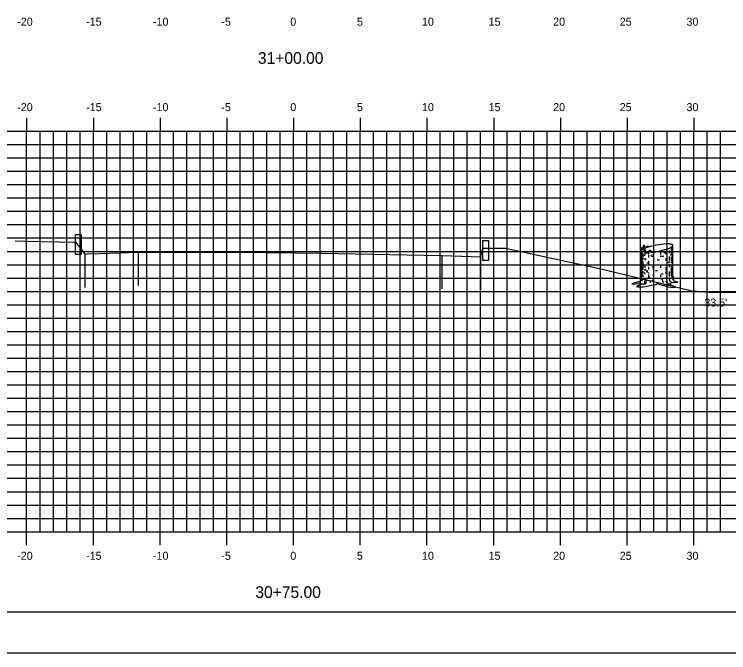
# Model space of a CAD drawing. Extents: x 1037709 to 1037879, y 394883 to 394993.
# Drawn here: x 1037771.2 to 1037824.8, y 394882.6 to 394930.4 of the extents above; entities that cross this region are included whole.
import ezdxf

# ---------------------------------------------------------------- set-up
doc = ezdxf.new("R2010")
doc.units = 0
for name, color, linetype in [('BORDER', 7, 'Continuous'), ('D_Text_Standard', 7, 'Continuous'), ('H_V ANNOTATION', 7, 'Continuous'), ('MAJOR', 7, 'Continuous'), ('MINOR', 7, 'Continuous'), ('PLOT BOUNDARY', 7, 'Continuous'), ('S_Curb_Type_1', 7, 'Continuous'), ('S_Roadway_Centerline', 7, 'Continuous'), ('S_Roadway_Edge_Pavement', 7, 'Continuous'), ('S_Roadway_Edge_TW', 7, 'Continuous'), ('S_Trees_Decid_Pay', 7, 'Continuous')]:
    doc.layers.add(name, color=color, linetype=linetype)

msp = doc.modelspace()

# ---------------------------------------------------------------- linework, layer by layer
at = {"layer": 'BORDER'}
msp.add_line((1037717.157, 394885.686), (1037877.157, 394885.686), dxfattribs=at)
at = {"layer": 'MAJOR'}
for p, q in [((1037772.157, 394922.688), (1037772.157, 394921.686)), ((1037777.157, 394922.688), (1037777.157, 394921.686)), ((1037782.157, 394922.688), (1037782.157, 394921.686)), ((1037787.157, 394922.688), (1037787.157, 394921.686)), ((1037792.157, 394922.688), (1037792.157, 394921.686)), ((1037797.157, 394922.688), (1037797.157, 394921.686)), ((1037802.157, 394922.688), (1037802.157, 394921.686)), ((1037807.157, 394922.688), (1037807.157, 394921.686)), ((1037812.157, 394922.688), (1037812.157, 394921.686)), ((1037817.157, 394922.688), (1037817.157, 394921.686)), ((1037822.157, 394922.688), (1037822.157, 394921.686)), ((1037722.157, 394921.686), (1037862.157, 394921.686)), ((1037772.157, 394891.686), (1037772.157, 394921.686)), ((1037777.157, 394891.686), (1037777.157, 394921.686)), ((1037782.157, 394891.686), (1037782.157, 394921.686)), ((1037787.157, 394891.686), (1037787.157, 394921.686)), ((1037792.157, 394891.686), (1037792.157, 394921.686)), ((1037797.157, 394891.686), (1037797.157, 394921.686)), ((1037802.157, 394891.686), (1037802.157, 394921.686)), ((1037807.157, 394891.686), (1037807.157, 394921.686)), ((1037812.157, 394891.686), (1037812.157, 394921.686)), ((1037817.157, 394891.686), (1037817.157, 394921.686)), ((1037822.157, 394891.686), (1037822.157, 394921.686)), ((1037722.157, 394916.686), (1037862.157, 394916.686)), ((1037722.157, 394911.686), (1037862.157, 394911.686)), ((1037722.157, 394906.686), (1037862.157, 394906.686)), ((1037722.157, 394901.686), (1037862.157, 394901.686)), ((1037722.157, 394896.686), (1037862.157, 394896.686)), ((1037722.157, 394891.686), (1037862.157, 394891.686)), ((1037772.157, 394890.684), (1037772.157, 394891.686)), ((1037777.157, 394890.684), (1037777.157, 394891.686)), ((1037782.157, 394890.684), (1037782.157, 394891.686)), ((1037787.157, 394890.684), (1037787.157, 394891.686)), ((1037792.157, 394890.684), (1037792.157, 394891.686)), ((1037797.157, 394890.684), (1037797.157, 394891.686)), ((1037802.157, 394890.684), (1037802.157, 394891.686)), ((1037807.157, 394890.684), (1037807.157, 394891.686)), ((1037812.157, 394890.684), (1037812.157, 394891.686)), ((1037817.157, 394890.684), (1037817.157, 394891.686)), ((1037822.157, 394890.684), (1037822.157, 394891.686))]:
    msp.add_line(p, q, dxfattribs=at)
at = {"layer": 'MINOR'}
for p, q in [((1037773.157, 394891.686), (1037773.157, 394921.686)), ((1037774.157, 394891.686), (1037774.157, 394921.686)), ((1037775.157, 394891.686), (1037775.157, 394921.686)), ((1037776.157, 394891.686), (1037776.157, 394921.686)), ((1037778.157, 394891.686), (1037778.157, 394921.686)), ((1037779.157, 394891.686), (1037779.157, 394921.686)), ((1037780.157, 394891.686), (1037780.157, 394921.686)), ((1037781.157, 394891.686), (1037781.157, 394921.686)), ((1037783.157, 394891.686), (1037783.157, 394921.686)), ((1037784.157, 394891.686), (1037784.157, 394921.686)), ((1037785.157, 394891.686), (1037785.157, 394921.686)), ((1037786.157, 394891.686), (1037786.157, 394921.686)), ((1037788.157, 394891.686), (1037788.157, 394921.686)), ((1037789.157, 394891.686), (1037789.157, 394921.686)), ((1037790.157, 394891.686), (1037790.157, 394921.686)), ((1037791.157, 394891.686), (1037791.157, 394921.686)), ((1037793.157, 394891.686), (1037793.157, 394921.686)), ((1037794.157, 394891.686), (1037794.157, 394921.686)), ((1037795.157, 394891.686), (1037795.157, 394921.686)), ((1037796.157, 394891.686), (1037796.157, 394921.686)), ((1037798.157, 394891.686), (1037798.157, 394921.686)), ((1037799.157, 394891.686), (1037799.157, 394921.686)), ((1037800.157, 394891.686), (1037800.157, 394921.686)), ((1037801.157, 394891.686), (1037801.157, 394921.686)), ((1037803.157, 394891.686), (1037803.157, 394921.686)), ((1037804.157, 394891.686), (1037804.157, 394921.686)), ((1037805.157, 394891.686), (1037805.157, 394921.686)), ((1037806.157, 394891.686), (1037806.157, 394921.686)), ((1037808.157, 394891.686), (1037808.157, 394921.686)), ((1037809.157, 394891.686), (1037809.157, 394921.686)), ((1037810.157, 394891.686), (1037810.157, 394921.686)), ((1037811.157, 394891.686), (1037811.157, 394921.686)), ((1037813.157, 394891.686), (1037813.157, 394921.686)), ((1037814.157, 394891.686), (1037814.157, 394921.686)), ((1037815.157, 394891.686), (1037815.157, 394921.686)), ((1037816.157, 394891.686), (1037816.157, 394921.686)), ((1037818.157, 394891.686), (1037818.157, 394921.686)), ((1037819.157, 394891.686), (1037819.157, 394921.686)), ((1037820.157, 394891.686), (1037820.157, 394921.686)), ((1037821.157, 394891.686), (1037821.157, 394921.686)), ((1037823.157, 394891.686), (1037823.157, 394921.686)), ((1037824.157, 394891.686), (1037824.157, 394921.686)), ((1037722.157, 394920.686), (1037862.157, 394920.686)), ((1037722.157, 394919.686), (1037862.157, 394919.686)), ((1037722.157, 394918.686), (1037862.157, 394918.686)), ((1037722.157, 394917.686), (1037862.157, 394917.686)), ((1037722.157, 394915.686), (1037862.157, 394915.686)), ((1037722.157, 394914.686), (1037862.157, 394914.686)), ((1037722.157, 394913.686), (1037862.157, 394913.686)), ((1037722.157, 394912.686), (1037862.157, 394912.686)), ((1037722.157, 394910.686), (1037862.157, 394910.686)), ((1037722.157, 394909.686), (1037862.157, 394909.686)), ((1037722.157, 394908.686), (1037862.157, 394908.686)), ((1037722.157, 394907.686), (1037862.157, 394907.686)), ((1037722.157, 394905.686), (1037862.157, 394905.686)), ((1037722.157, 394904.686), (1037862.157, 394904.686)), ((1037722.157, 394903.686), (1037862.157, 394903.686)), ((1037722.157, 394902.686), (1037862.157, 394902.686)), ((1037722.157, 394900.686), (1037862.157, 394900.686)), ((1037722.157, 394899.686), (1037862.157, 394899.686)), ((1037722.157, 394898.686), (1037862.157, 394898.686)), ((1037722.157, 394897.686), (1037862.157, 394897.686)), ((1037722.157, 394895.686), (1037862.157, 394895.686)), ((1037722.157, 394894.686), (1037862.157, 394894.686)), ((1037722.157, 394893.686), (1037862.157, 394893.686)), ((1037722.157, 394892.686), (1037862.157, 394892.686))]:
    msp.add_line(p, q, dxfattribs=at)
at = {"layer": 'PLOT BOUNDARY'}
msp.add_lwpolyline([(1037709.064, 394882.627), (1037879.064, 394882.627), (1037879.064, 394992.627), (1037709.064, 394992.627)], close=True, dxfattribs=at)
at = {"layer": 'S_Curb_Type_1'}
for points in [[(1037775.828, 394913.952), (1037776.244, 394913.952), (1037776.244, 394912.452), (1037775.828, 394912.452)], [(1037806.351, 394913.51), (1037806.768, 394913.51), (1037806.768, 394912.01), (1037806.351, 394912.01)]]:
    msp.add_lwpolyline(points, close=True, dxfattribs=at)
at = {"layer": 'S_Roadway_Centerline'}
msp.add_lwpolyline([(1037771.303, 394913.468), (1037772.043, 394913.454), (1037775.828, 394913.369), (1037776.383, 394912.646), (1037776.528, 394912.481), (1037776.688, 394912.497), (1037777.677, 394912.527), (1037780.514, 394912.634), (1037790.122, 394912.588), (1037792.25, 394912.579), (1037794.199, 394912.547), (1037803.27, 394912.372), (1037804.774, 394912.324), (1037806.176, 394912.282), (1037806.341, 394912.89), (1037806.351, 394912.926), (1037806.4, 394912.926), (1037808.033, 394912.919), (1037815.077, 394911.41), (1037822.032, 394909.722), (1037823.625, 394909.598), (1037825.706, 394909.621)], dxfattribs=at)
at = {"layer": 'S_Roadway_Edge_Pavement'}
for p, q in [((1037776.528, 394912.481), (1037776.528, 394909.981)), ((1037806.176, 394912.282), (1037806.176, 394909.782))]:
    msp.add_line(p, q, dxfattribs=at)
at = {"layer": 'S_Roadway_Edge_TW'}
for p, q in [((1037780.514, 394912.634), (1037780.514, 394910.134)), ((1037803.27, 394912.372), (1037803.27, 394909.872))]:
    msp.add_line(p, q, dxfattribs=at)
at = {"layer": 'S_Trees_Decid_Pay'}
for p, q in [((1037820.53, 394913.04), (1037820.53, 394912.92)), ((1037818.256, 394912.637), (1037818.256, 394912.382)), ((1037818.405, 394912.837), (1037818.405, 394912.662)), ((1037818.49, 394912.588), (1037818.49, 394912.383)), ((1037818.751, 394912.59), (1037818.751, 394912.471)), ((1037819.662, 394912.728), (1037819.662, 394912.448)), ((1037820.045, 394912.829), (1037820.045, 394912.742)), ((1037820.045, 394912.601), (1037820.045, 394912.462)), ((1037820.317, 394912.742), (1037820.317, 394912.551)), ((1037820.45, 394912.996), (1037820.45, 394912.742)), ((1037820.45, 394912.646), (1037820.45, 394912.382)), ((1037820.53, 394912.868), (1037820.53, 394912.654)), ((1037820.53, 394912.609), (1037820.53, 394912.271)), ((1037818.256, 394912.285), (1037818.256, 394911.816)), ((1037818.342, 394912.491), (1037818.342, 394912.279)), ((1037818.342, 394912.214), (1037818.342, 394912.065)), ((1037818.49, 394912.176), (1037818.49, 394912.022)), ((1037818.751, 394912.419), (1037818.751, 394912.234)), ((1037818.989, 394912.318), (1037818.994, 394912.425)), ((1037819.116, 394912.491), (1037819.116, 394912.311)), ((1037819.662, 394912.382), (1037819.662, 394912.279)), ((1037820.045, 394912.176), (1037820.045, 394911.985)), ((1037820.317, 394912.299), (1037820.317, 394912.022)), ((1037820.317, 394911.977), (1037820.317, 394911.868)), ((1037820.45, 394912.285), (1037820.45, 394911.977)), ((1037820.53, 394912.154), (1037820.53, 394911.793)), ((1037818.256, 394911.765), (1037818.256, 394911.631)), ((1037818.256, 394911.573), (1037818.256, 394911.248)), ((1037818.342, 394911.888), (1037818.342, 394911.588)), ((1037818.342, 394911.55), (1037818.342, 394911.307)), ((1037818.49, 394911.659), (1037818.49, 394911.439)), ((1037818.751, 394911.948), (1037818.751, 394911.719)), ((1037818.751, 394911.521), (1037818.751, 394911.336)), ((1037819.116, 394911.533), (1037819.116, 394911.336)), ((1037819.662, 394911.668), (1037819.662, 394911.447)), ((1037820.045, 394911.505), (1037820.045, 394911.297)), ((1037820.317, 394911.733), (1037820.317, 394911.505)), ((1037820.45, 394911.888), (1037820.45, 394911.822)), ((1037820.45, 394911.588), (1037820.45, 394911.49)), ((1037820.45, 394911.439), (1037820.45, 394911.079)), ((1037820.53, 394911.756), (1037820.53, 394911.307)), ((1037818.256, 394911.219), (1037818.256, 394910.799)), ((1037818.342, 394911.196), (1037818.342, 394911.056)), ((1037818.342, 394910.924), (1037818.342, 394910.768)), ((1037818.49, 394911.339), (1037818.49, 394911.219)), ((1037818.49, 394911.068), (1037818.49, 394910.969)), ((1037818.751, 394911.101), (1037818.751, 394911.025)), ((1037818.751, 394910.947), (1037818.751, 394910.774)), ((1037819.116, 394910.953), (1037819.116, 394910.85)), ((1037819.662, 394910.947), (1037819.662, 394910.774)), ((1037820.045, 394911.175), (1037820.045, 394910.976)), ((1037820.317, 394911.175), (1037820.317, 394910.792)), ((1037820.45, 394911.027), (1037820.45, 394910.86)), ((1037820.53, 394911.242), (1037820.53, 394910.96)), ((1037818.259, 394910.696), (1037818.244, 394910.578)), ((1037820.04, 394910.719), (1037820.12, 394910.587))]:
    msp.add_line(p, q, dxfattribs=at)
for points in [[(1037818.205, 394912.911), (1037818.205, 394910.774), (1037818.185, 394910.632), (1037818.179, 394910.506), (1037818.135, 394910.42), (1037818.043, 394910.37), (1037817.907, 394910.37), (1037817.664, 394910.315), (1037817.497, 394910.265), (1037817.639, 394910.235), (1037817.876, 394910.272), (1037818.086, 394910.259), (1037818.347, 394910.265), (1037818.471, 394910.284), (1037818.502, 394910.241), (1037818.564, 394910.284), (1037818.465, 394910.216), (1037818.23, 394910.191), (1037818, 394910.13), (1037817.87, 394910.059), (1037817.969, 394910.016), (1037818.391, 394910.035), (1037818.669, 394910.078), (1037818.967, 394910.154), (1037819.254, 394910.191), (1037819.359, 394910.191), (1037819.377, 394910.272), (1037819.445, 394910.278), (1037819.612, 394910.191), (1037819.898, 394910.135), (1037820.196, 394910.028), (1037820.656, 394909.979), (1037820.81, 394909.992), (1037820.468, 394910.142), (1037820.265, 394910.173), (1037820.277, 394910.247), (1037820.536, 394910.346), (1037820.712, 394910.377), (1037820.952, 394910.389), (1037820.754, 394910.426), (1037820.693, 394910.463), (1037820.668, 394910.549), (1037820.656, 394910.719), (1037820.611, 394910.805), (1037820.582, 394911.046), (1037820.582, 394913.131)], [(1037818.561, 394912.584), (1037818.553, 394912.728), (1037818.508, 394912.72), (1037818.494, 394913.095), (1037818.399, 394913.103), (1037818.385, 394913.183), (1037818.347, 394912.845), (1037818.302, 394912.94), (1037818.282, 394912.786), (1037818.205, 394912.911), (1037818.211, 394912.721)], [(1037818.584, 394912.95), (1037818.605, 394913.057), (1037818.737, 394913.088), (1037818.744, 394913)], [(1037818.205, 394912.911), (1037818.251, 394912.934), (1037818.273, 394913), (1037818.325, 394913.023), (1037818.359, 394912.948)], [(1037818.723, 394912.588), (1037818.759, 394912.691), (1037818.825, 394912.697), (1037818.825, 394912.779), (1037818.899, 394912.786), (1037818.924, 394912.605)], [(1037820.158, 394911.311), (1037820.157, 394911.387), (1037820.149, 394911.454)], [(1037818.613, 394911.219), (1037818.605, 394911.145), (1037818.679, 394911.139), (1037818.693, 394911.256)], [(1037818.325, 394910.704), (1037818.319, 394910.578), (1037818.237, 394910.484)], [(1037818.471, 394910.284), (1037818.49, 394910.463), (1037818.551, 394910.599), (1037818.545, 394910.7)], [(1037818.662, 394910.531), (1037818.588, 394910.463), (1037818.57, 394910.364), (1037818.564, 394910.284)], [(1037819.114, 394910.667), (1037819.097, 394910.513), (1037818.899, 394910.432), (1037818.854, 394910.329)], [(1037819.679, 394910.658), (1037819.782, 394910.607), (1037819.797, 394910.401), (1037819.9, 394910.372)], [(1037820.265, 394910.173), (1037820.178, 394910.315), (1037820.046, 394910.457)], [(1037820.334, 394910.733), (1037820.334, 394910.527), (1037820.392, 394910.418), (1037820.489, 394910.401)], [(1037820.475, 394910.807), (1037820.546, 394910.704), (1037820.546, 394910.578)], [(1037820.532, 394910.887), (1037820.592, 394910.727), (1037820.606, 394910.601), (1037820.598, 394910.504)]]:
    msp.add_lwpolyline(points, dxfattribs=at)
for centre, radius, start, end in [((1037820.495, 394907.13), 6.126, 100.7779, 107.8613), ((1037820.495, 394907.13), 6.126, 93.6944, 100.7779), ((1037820.184, 394911.946), 1.299, 78.2779, 93.6944), ((1037820.351, 394912.749), 0.48, 69.9843, 78.2779), ((1037820.223, 394913.419), 0.48, 303.2779, 311.5714), ((1037820.459, 394913.046), 0.164, 55.7779, 69.9843), ((1037820.432, 394913.183), 0.164, 311.5714, 325.7779), ((1037820.49, 394913.092), 0.107, 45.9547, 55.7779), ((1037820.52, 394913.123), 0.0645, 33.2779, 45.9547), ((1037820.479, 394913.151), 0.107, 325.7779, 335.6011), ((1037820.529, 394913.129), 0.0544, 22.46, 33.2779), ((1037820.518, 394913.134), 0.0645, 335.6011, 348.2779), ((1037820.536, 394913.132), 0.0467, 10.7779, 22.46), ((1037820.528, 394913.132), 0.0544, 348.2779, 359.0957), ((1037820.536, 394913.132), 0.0467, 359.0957, 10.7779), ((1037818.253, 394912.543), 0.0476, 180, 191.6815), ((1037818.261, 394912.544), 0.0554, 191.6815, 202.5), ((1037818.27, 394912.548), 0.0657, 202.5, 215.1737), ((1037818.306, 394912.573), 0.109, 215.1737, 225), ((1037819.015, 394911.724), 1.299, 107.8613, 113.3069), ((1037818.604, 394913.882), 1.299, 268.1289, 273.6944), ((1037818.293, 394918.699), 6.126, 273.6944, 274.0246), ((1037818.293, 394918.699), 6.126, 275.9147, 280.7779), ((1037818.293, 394918.699), 6.126, 280.7779, 287.8613), ((1037819.395, 394918.482), 5.916, 274.9515, 276.3087), ((1037819.773, 394914.105), 1.299, 287.8613, 303.2779), ((1037819.971, 394913.894), 1.292, 285.5651, 289.0916), ((1037820.443, 394912.875), 0.166, 301.67, 315), ((1037820.482, 394912.573), 0.109, 315, 324.8263), ((1037820.483, 394912.834), 0.109, 315, 324.8263), ((1037820.518, 394912.548), 0.0657, 324.8263, 337.5), ((1037820.519, 394912.809), 0.0657, 324.8263, 337.5), ((1037820.527, 394912.544), 0.0554, 337.5, 348.3185), ((1037820.528, 394912.805), 0.0554, 337.5, 348.3185), ((1037818.253, 394912.022), 0.0476, 180, 191.6815), ((1037818.261, 394912.023), 0.0554, 191.6815, 202.5), ((1037818.27, 394912.027), 0.0657, 202.5, 215.1737), ((1037818.306, 394912.052), 0.109, 215.1737, 225), ((1037818.346, 394912.614), 0.166, 225, 239.1924), ((1037818.346, 394912.093), 0.166, 225, 239.1924), ((1037818.346, 394912.35), 0.166, 237.0378, 239.1924), ((1037818.509, 394912.623), 0.484, 239.1924, 247.5), ((1037818.818, 394913.369), 1.292, 247.5, 248.3537), ((1037818.818, 394913.633), 1.292, 250.6119, 255.2856), ((1037818.818, 394913.369), 1.292, 255.2856, 259.2632), ((1037819.394, 394918.221), 5.916, 266.0776, 267.3043), ((1037819.394, 394917.957), 5.916, 270.1162, 271.7708), ((1037819.394, 394918.221), 5.916, 273.5382, 274.8924), ((1037819.394, 394917.957), 5.916, 276.3184, 277.1546), ((1037819.97, 394913.369), 1.292, 277.1546, 278.3662), ((1037819.97, 394913.633), 1.292, 288.0829, 292.5), ((1037819.97, 394913.369), 1.292, 291.8071, 292.5), ((1037820.279, 394912.623), 0.484, 292.5, 300.8076), ((1037820.279, 394912.887), 0.484, 297.4162, 300.8076), ((1037820.442, 394912.614), 0.166, 300.8076, 315), ((1037820.442, 394912.35), 0.166, 300.8076, 301.6001), ((1037820.442, 394912.093), 0.166, 300.8076, 315), ((1037820.482, 394912.052), 0.109, 315, 324.8263), ((1037820.518, 394912.027), 0.0657, 324.8263, 337.5), ((1037820.527, 394912.023), 0.0554, 337.5, 348.3185), ((1037818.253, 394911.764), 0.0476, 180, 191.6815), ((1037818.253, 394911.499), 0.0476, 180, 191.6815), ((1037818.261, 394911.766), 0.0554, 191.6815, 202.5), ((1037818.261, 394911.5), 0.0554, 191.6815, 202.5), ((1037818.27, 394911.77), 0.0657, 202.5, 215.1737), ((1037818.27, 394911.504), 0.0657, 202.5, 215.1737), ((1037818.306, 394911.795), 0.109, 215.1737, 225), ((1037818.306, 394911.529), 0.109, 215.1737, 225), ((1037818.346, 394911.835), 0.166, 225, 239.1924), ((1037818.346, 394911.57), 0.166, 225, 239.1924), ((1037818.509, 394912.366), 0.484, 239.1924, 245.7725), ((1037818.818, 394913.112), 1.292, 247.5, 248.4842), ((1037818.818, 394912.855), 1.292, 247.5, 251.799), ((1037818.818, 394913.112), 1.292, 261.8726, 262.8454), ((1037819.394, 394917.7), 5.916, 262.8454, 263.7595), ((1037819.394, 394917.443), 5.916, 266.2721, 267.3043), ((1037819.97, 394913.112), 1.292, 279.2565, 285.6105), ((1037819.97, 394912.855), 1.292, 285.6105, 290.1001), ((1037820.279, 394912.366), 0.484, 294.6372, 300.8076), ((1037820.442, 394911.835), 0.166, 302.0694, 315), ((1037820.482, 394911.795), 0.109, 315, 324.8263), ((1037820.518, 394911.77), 0.0657, 324.8263, 337.5), ((1037820.527, 394911.766), 0.0554, 337.5, 348.3185), ((1037820.527, 394911.5), 0.0554, 337.5, 348.3185), ((1037818.253, 394910.97), 0.0476, 180, 191.6815), ((1037818.261, 394910.971), 0.0554, 191.6815, 202.5), ((1037818.27, 394910.975), 0.0657, 202.5, 215.1737), ((1037818.306, 394911), 0.109, 215.1737, 225), ((1037818.346, 394911.041), 0.166, 225, 239.1924), ((1037818.509, 394911.843), 0.484, 239.1924, 247.5), ((1037818.509, 394911.314), 0.484, 239.1924, 247.5), ((1037818.509, 394911.571), 0.484, 242.734, 247.5), ((1037818.818, 394912.589), 1.292, 247.5, 248.3537), ((1037818.818, 394912.317), 1.292, 251.3664, 255.2856), ((1037818.818, 394912.589), 1.292, 255.2856, 259.2463), ((1037819.394, 394917.177), 5.916, 268.9207, 270), ((1037819.394, 394917.177), 5.916, 270, 270.2757), ((1037819.394, 394916.905), 5.916, 273.2637, 274.461), ((1037819.394, 394917.177), 5.916, 276.3184, 277.1546), ((1037819.394, 394916.905), 5.916, 276.3184, 277.1546), ((1037819.97, 394912.589), 1.292, 277.1546, 278.3795), ((1037819.97, 394912.317), 1.292, 277.1546, 278.3662), ((1037819.97, 394912.317), 1.292, 285.6105, 289.1534), ((1037820.279, 394911.843), 0.484, 292.5, 300.8076), ((1037820.442, 394911.57), 0.166, 300.8076, 302.0694), ((1037820.442, 394911.298), 0.166, 302.0694, 315), ((1037820.482, 394911.257), 0.109, 315, 324.8263), ((1037820.518, 394911.232), 0.0657, 324.8263, 337.5), ((1037820.527, 394911.229), 0.0554, 337.5, 348.3185), ((1037818.818, 394912.06), 1.292, 247.5, 248.3537), ((1037819.394, 394916.648), 5.916, 263.7831, 264.7656), ((1037819.979, 394912.064), 1.292, 291.3696, 292.0604), ((1037820.279, 394911.314), 0.484, 292.5, 296.5499)]:
    msp.add_arc(centre, radius, start, end, dxfattribs=at)

# ---------------------------------------------------------------- texts
at = {"layer": 'D_Text_Standard'}
msp.add_text("33.5'", height=0.6, dxfattribs=at).set_placement((1037822.943, 394908.553))
at = {"layer": 'H_V ANNOTATION'}
for s, height, p in [('-20', 0.6, (1037771.45, 394929.586)), ('-15', 0.6, (1037776.614, 394929.586)), ('-10', 0.6, (1037781.622, 394929.586)), ('-5', 0.6, (1037786.747, 394929.586)), ('0', 0.6, (1037791.916, 394929.586)), ('5', 0.6, (1037796.908, 394929.586)), ('10', 0.6, (1037801.782, 394929.586)), ('15', 0.6, (1037806.774, 394929.586)), ('20', 0.6, (1037811.611, 394929.586)), ('25', 0.6, (1037816.603, 394929.586)), ('30', 0.6, (1037821.606, 394929.586)), ('31+00.00', 0.875, (1037789.488, 394926.729)), ('-20', 0.6, (1037771.45, 394923.186)), ('-15', 0.6, (1037776.614, 394923.186)), ('-10', 0.6, (1037781.622, 394923.186)), ('-5', 0.6, (1037786.747, 394923.186)), ('0', 0.6, (1037791.916, 394923.186)), ('5', 0.6, (1037796.908, 394923.186)), ('10', 0.6, (1037801.782, 394923.186)), ('15', 0.6, (1037806.774, 394923.186)), ('20', 0.6, (1037811.611, 394923.186)), ('25', 0.6, (1037816.603, 394923.186)), ('30', 0.6, (1037821.606, 394923.186)), ('-20', 0.6, (1037771.45, 394889.586)), ('-15', 0.6, (1037776.614, 394889.586)), ('-10', 0.6, (1037781.622, 394889.586)), ('-5', 0.6, (1037786.747, 394889.586)), ('0', 0.6, (1037791.916, 394889.586)), ('5', 0.6, (1037796.908, 394889.586)), ('10', 0.6, (1037801.782, 394889.586)), ('15', 0.6, (1037806.774, 394889.586)), ('20', 0.6, (1037811.611, 394889.586)), ('25', 0.6, (1037816.603, 394889.586)), ('30', 0.6, (1037821.606, 394889.586)), ('30+75.00', 0.875, (1037789.293, 394886.729))]:
    msp.add_text(s, height=height, dxfattribs=at).set_placement(p)
at = {"layer": 'S_Roadway_Centerline'}
for s, p in [('C', (1037792.245, 394912.579)), ('L', (1037792.25, 394912.572))]:
    msp.add_text(s, height=0.0146, dxfattribs=at).set_placement(p)

doc.saveas('drawing.dxf')
